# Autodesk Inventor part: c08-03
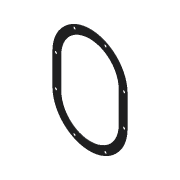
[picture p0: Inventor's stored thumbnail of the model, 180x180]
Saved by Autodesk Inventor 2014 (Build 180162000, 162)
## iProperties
Created: 2010-12
Part Number: c08-03
Material: Rubber
Document SubType Name: Modeling
Designer: Thom Tremblay
Mass: 7.85962 g
Surface Area: 147.076 cm^2
Volume: 8.4512 cm^3
Density: 0.93 g/cm^3
Appearance: Rubber - Black - Version 1.1
Author: Thom Tremblay
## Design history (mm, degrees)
sketch "Sketch1"
  geometry: L1 (-60, 33.338)-(-60, -16.662) reference; L2 (60, -16.662)-(60, 33.338) reference; L3 (-46.998, -16.662)-(-46.998, 33.338) reference; L4 (46.998, 33.338)-(46.998, -16.662) reference; C1 r 1.621 at (-55, -17.463) reference; C2 r 1.621 at (-25, -66.452) reference; C3 r 1.621 at (25, -66.452) reference; C4 r 1.621 at (55, -17.462) reference; C5 r 1.621 at (55, 33.338) reference; C6 r 1.621 at (25, 82.327) reference; C7 r 1.621 at (-25, 82.327) reference; C8 r 1.621 at (-55, 33.337) reference; A1 r 60 centre (0, -16.662) between (-60, -16.662) and (-18.704, -73.673) reference; A2 r 60 centre (0, 33.338) between (60, 33.338) and (-60, 33.338) reference; A3 r 46.998 centre (0, -16.662) between (-46.998, -16.662) and (46.998, -16.662) reference; A4 r 46.998 centre (0, 33.338) between (46.998, 33.338) and (-46.998, 33.338) reference; A5 r 60.082 centre (0, -16.662) between (-16.251, -74.505) and (16.251, -74.505) reference; A6 r 60 centre (0, -16.662) between (18.704, -73.673) and (60, -16.662) reference; 21 further points
extrude "Extrusion1" new body sketch "Sketch1" distance "d0" = 1.27; taper "d1" = 0 deg
node "Hole3"
body "Solid1"
node "Reference1"
sketch "Sketch3"
  geometry: 8 further points
hole "Hole2" sketch "Sketch3" diameter "d9" = 4.49999; stored, may be unused: countersink angle "d13" = 82 deg, drill point angle "d15" = 0 deg; dims "d10" = 19.05, "d11" = 9.525, "d12" = 6.35, "d14" = 25.4
